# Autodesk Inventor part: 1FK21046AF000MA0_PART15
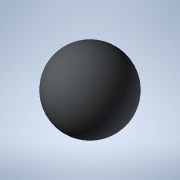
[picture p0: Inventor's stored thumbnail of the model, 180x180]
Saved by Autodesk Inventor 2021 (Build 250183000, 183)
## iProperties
Created: 2025-04
Part Number: 1FK21046AF000MA0_PART15
Material: Generic
Catalog Web Link: www.3dfindit.com
Description: -Servo synchronous motor
Document SubType Name: Modeling
Designer: psAdmin
Mass: 0.137258 g
Surface Area: 1.2868 cm^2
Volume: 0.137258 cm^3
Density: 1 g/cm^3
Appearance: PSOLRGB-212-217-219
Category: PARTsolutions
Title: 1FK21046AF000MA0_PART15
Author: Cadenas PARTsolutions
Comments: Servo synchronous motor
Sending System: PARTsolutions
Preprocessor: ST-DEVELOPER v19.3
PSOL_IDENT_0: {$CADENAS_DATA/23d-libs/siemens_ag/_cat_/1c/1f/1fk21046af000ma0.prj},216 {VTYP=3D},{NB=1FK21046AF000
PSOL_IDENT_1: MA0_PART15},{LINA=1FK21046AF000MA0_PART15},{NN=1FK21046AF000MA0_PART15},{NOPRJ=TRUE},{DATE=19.08.202
PSOL_IDENT_2: 5 14:00:28},{GEOMDATE=30.07.2025 02:02:08},{VERSION=},{LINEID=10},{WBVAR=},{WBNUMERIC=}  {NB=1FK2104
PSOL_IDENT_3: 6AF000MA0_PART15},{LINA=1FK21046AF000MA0_PART15},{KT=DUMMY},{PREVIEW=../../../_pool_/cb/72/p_d211_xx
PSOL_IDENT_4: _00434j.png},{DESCSHORT=SIMOTICS S-1FK2 HD, SINAMICS S210 3AC 400V-480V, 3.2 Nm, 3000 rpm},{DESCLONG=
PSOL_IDENT_5: SIMOTICS S-1FK2 HD servo motor M0=3.2 Nm; PN = 1 kW at nN=3000 rpm (380-480 V); PN = 0.5 kW at nN=15
PSOL_IDENT_6: 00 rpm (200-240 V); degree of protection IP64; cylindrical shaft D19x40mm; absolute encoder 22-bit +
PSOL_IDENT_7: 12-bit multiturn (encoder AM22DQC); with OCC interface; plug size M17, rotatable; SIMOTICS S-1FK2 s
PSOL_IDENT_8: ervomotorfor a wide range of uses in industrial environments. SIMOTICS S‑1FK2 servomotors are compac
PSOL_IDENT_9: t synchronous motors with a high dynamic performance that set themselves apart as a result of their
PSOL_IDENT_10: high power density, degree of protection and overload capability. The motors are available in two va
PSOL_IDENT_11: riants: as High Dynamic variant (highest dynamic performance as a result of the low intrinsic moment
PSOL_IDENT_12: of inertia for applications demanding a high dynamic performance with low moved masses) - and as Co
PSOL_IDENT_13: mpact variant (precise and stable closed-loop control for medium up to large moved masses as a resul
PSOL_IDENT_14: t of a medium intrinsic moment of inertia). SIMOTICSS‑1FK2 servomotors fully exploit their strengths
PSOL_IDENT_15: in a system with the SINAMICSS210 frequency converter and simple connection using the one cable con
PSOL_IDENT_16: nection (OCC). Advantages include the short control and positioning times, fast and precise correcti
PSOL_IDENT_17: on of disturbing quantities as well as stable control with a high dynamic performance. The servo mot
PSOL_IDENT_18: ors can be configured to address a wide range of requirements. For example with and without holding
PSOL_IDENT_19: brake, IP64 or IP65 degree of protection, singleturn or multiturn absolute encoders - to name just a
PSOL_IDENT_20: few. Further, the servomotors are available in different shaft heights extending from 20 to 100. A
PSOL_IDENT_21: shaft sealing ring is available to achieve an IP65 degree of protection and for subsequent mounting
PSOL_IDENT_22: at the motor or as spare part. SIMOTICS - the optimum motor for each and every motion control applic
PSOL_IDENT_23: ation.},{INTNO=195125049666},{SUPPLIERALTNO=1FK2104-6AF00-0MA0},{MANUID=1FK21046AF000MA0},{MANUNAME=
PSOL_IDENT_24: Siemens},{MANUTYPEDESC=Synchronous motor 1FK2-HD 3.2 NM},{AAU732=SIMOTICS},{AAO057=S-1FK2},{AAU734=S
PSOL_IDENT_25: IMOTICS S-1FK2 HD servo motor M0=3.2 Nm; PN = 1 kW at nN=3000 rpm (380-480 V); PN = 0.5 kW at nN=150
PSOL_IDENT_26: 0 rpm (200-240 V); degree of protection IP64; cylindrical shaft D19x40mm; absolute encoder 22-bit +
PSOL_IDENT_27: 12-bit multiturn (encoder AM22DQC); with OCC interface; plug size M17, rotatable;},{AAW338=Synchrono
PSOL_IDENT_28: us motor 1FK2-HD 3.2 NM},{AAO742=SIMOTICS},{AAO663=4042948694374},{NOCUPEROU=1},{PRICEQUANTITY=1},{Q
PSOL_IDENT_29: UANTITYMIN=1},{QUANTITYINT=1},{CTN=85015220},{COO=DE},{AAO676=1FK2104-6AF00-0MA0},{AAO677=Siemens AG
PSOL_IDENT_30: },{ORDERUNIT=C62},{CONTENTUNIT=C62}
NB: 1FK21046AF000MA0_PART15
NT: Servo synchronous motor
NBSYN: $MANUID._PART15
LINA: 1FK21046AF000MA0_PART15
CATALOG: SIEMENS
PREVIEW: ../../../_pool_/cb/72/p_d211_xx_00434j.png
DESCSHORT: SIMOTICS S-1FK2 HD, SINAMICS S210 3AC 400V-480V, 3.2 Nm, 3000 rpm
DESCLONG: SIMOTICS S-1FK2 HD servo motor M0=3.2 Nm; PN = 1 kW at nN=3000 rpm (380-480 V); PN = 0.5 kW at nN=1500 rpm (200-240 V); degree of protection IP64; cylindrical s
INTNO: 195125049666
SUPPLIERALTNO: 1FK2104-6AF00-0MA0
MANUID: 1FK21046AF000MA0
MANUNAME: Siemens
MANUTYPEDESC: Synchronous motor 1FK2-HD 3.2 NM
AAU732: SIMOTICS
AAO057: S-1FK2
AAU734: SIMOTICS S-1FK2 HD servo motor M0=3.2 Nm; PN = 1 kW at nN=3000 rpm (380-480 V); PN = 0.5 kW at nN=1500 rpm (200-240 V); degree of protection IP64; cylindrical s
AAW338: Synchronous motor 1FK2-HD 3.2 NM
AAO742: SIMOTICS
AAO663: 4042948694374.0
NOCUPEROU: 1
PRICEQUANTITY: 1
QUANTITYMIN: 1
QUANTITYINT: 1
CTN: 85015220
COO: DE
ARTICLENO: 1FK21046AF000MA0_PART15
BOMINFO: 1FK21046AF000MA0_PART15
CREATOR: CADENAS GmbH
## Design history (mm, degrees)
feature "2025_04_17_15_39_11_0412"
body "Solid1"
